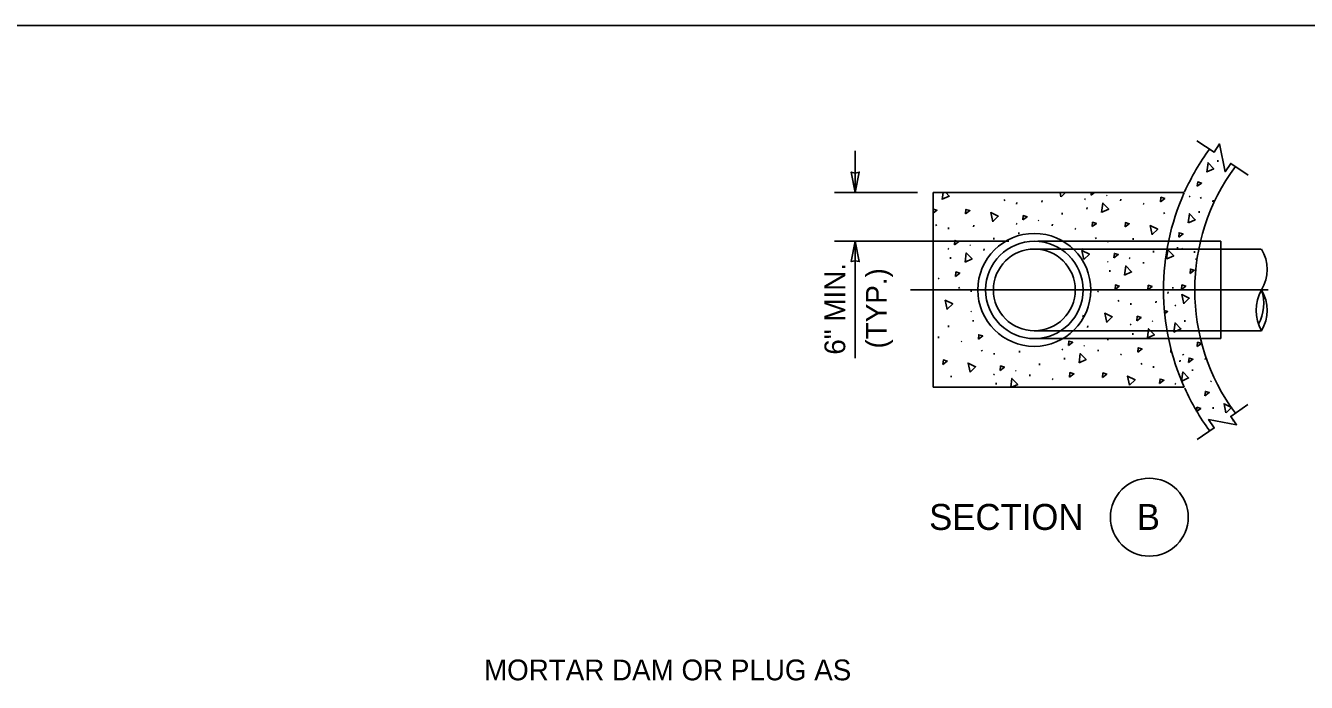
# Model space of a CAD drawing. Extents: x 99862 to 103151, y 100000 to 102076.
# Drawn here: x 101274 to 102261, y 101570 to 102076 of the extents above; entities that cross this region are included whole.
import ezdxf

# ---------------------------------------------------------------- set-up
doc = ezdxf.new("R2010")
doc.units = 0
for name, color, linetype in [('Level 1', 7, 'Continuous'), ('Level 15', 7, 'Continuous'), ('Level 17', 7, 'Continuous'), ('Level 19', 7, 'Continuous'), ('Level 20', 7, 'Continuous'), ('Level 27', 7, 'Continuous'), ('Level 9', 7, 'Continuous')]:
    doc.layers.add(name, color=color, linetype=linetype)

msp = doc.modelspace()

# ---------------------------------------------------------------- linework, layer by layer
at = {"layer": 'Level 1'}
for p, q in [((102051.16, 101903.5), (102194.29, 101903.5)), ((102179.16, 101909.5), (102053.84, 101909.5)), ((102194.7, 101909.5), (102179.16, 101909.5)), ((102194.7, 101909.5), (102194.7, 101834.5)), ((102194.75, 101903.5), (102225.99, 101903.5)), ((102231.31, 101872), (101955.67, 101872)), ((102051.16, 101840.5), (102194.29, 101840.5)), ((102179.16, 101834.5), (102053.84, 101834.5)), ((102194.7, 101834.5), (102179.16, 101834.5)), ((102194.98, 101840.5), (102226.21, 101840.5))]:
    msp.add_line(p, q, dxfattribs=at)
msp.add_lwpolyline([(99862, 99999.5), (103151, 99999.5), (103151, 102075.5), (99862, 102075.5)], close=True, dxfattribs=at)
for radius in [43.5, 37.5, 31.5]:
    msp.add_circle((102051.16, 101872), radius, dxfattribs=at)
for centre, radius, start, end in [((102334.48, 101872), 183.78, 143.86427, 155.72828), ((102334.48, 101872), 159.78, 143.51852, 216.48148), ((102198.94, 101887.75), 31.5, 330, 30), ((102253.49, 101856.25), 31.5, 150, 210), ((102194.23, 101861.5), 33.66, 331.70113, 18.1584), ((102198.94, 101856.25), 31.5, 330, 30), ((102334.48, 101872), 183.78, 204.34216, 216.23579)]:
    msp.add_arc(centre, radius, start, end, dxfattribs=at)
at = {"layer": 'Level 15'}
for p, q in [((101913.16, 101947), (101913.16, 101979)), ((101961.16, 101947), (101897.16, 101947)), ((102031.47, 101909.5), (101897.16, 101909.5)), ((101913.16, 101909.5), (101913.16, 101819.33))]:
    msp.add_line(p, q, dxfattribs=at)
for points in [[(102176.31, 101986.9), (102189.6, 101977.99), (102193.91, 101984.43), (102198.15, 101962.94), (102202.46, 101969.37), (102215.75, 101960.46)], [(102176.59, 101756.7), (102189.76, 101765.78), (102185.36, 101772.16), (102206.9, 101768.2), (102202.5, 101774.58), (102215.67, 101783.66)]]:
    msp.add_lwpolyline(points, dxfattribs=at)
for points in [[(101913.16, 101947), (101910.08, 101962.72), (101913.16, 101961.99), (101916.25, 101962.72)], [(101913.16, 101909.5), (101916.25, 101893.77), (101913.16, 101894.5), (101910.08, 101893.77)]]:
    msp.add_lwpolyline(points, close=True, dxfattribs=at)
at = {"layer": 'Level 17'}
for p, q in [((101973.16, 101947), (101973.16, 101797)), ((102166.7, 101947), (101973.16, 101947)), ((102166.7, 101797), (101973.16, 101797))]:
    msp.add_line(p, q, dxfattribs=at)
msp.add_arc((102334.48, 101872), 183.78, 155.91485, 204.08515, dxfattribs=at)
at = {"layer": 'Level 19'}
for p, q in [((102192.41, 101970.63), (102192.49, 101971.85)), ((102028.01, 101941.57), (102028.51, 101940.56)), ((102057.05, 101939.69), (102057.14, 101940.91)), ((102089.81, 101942.22), (102090.53, 101941.7)), ((102106.63, 101944.98), (102107.35, 101944.45)), ((102117.64, 101940.59), (102117.72, 101941.81)), ((102170.54, 101944.23), (102171.27, 101943.7)), ((102179.2, 101943.42), (102179.7, 101942.41)), ((102188.74, 101939.87), (102188.82, 101941.09)), ((102037.55, 101938.02), (102037.63, 101939.24)), ((102072.61, 101930.01), (102072.7, 101931.23)), ((102091.72, 101934.2), (102091.81, 101935.43)), ((102134.96, 101938.43), (102135.68, 101937.9)), ((102150.85, 101931.52), (102151.35, 101930.51)), ((102178.1, 101931.41), (102178.19, 101932.63)), ((101975.38, 101922.41), (101975.88, 101921.4)), ((101984.93, 101918.86), (101985.01, 101920.09)), ((102004.43, 101920.54), (102004.51, 101921.76)), ((102037.19, 101923.07), (102037.91, 101922.54)), ((102054, 101925.82), (102054.72, 101925.3)), ((102065.02, 101921.44), (102065.1, 101922.66)), ((102019.99, 101910.86), (102020.07, 101912.08)), ((102039.1, 101915.05), (102039.19, 101916.27)), ((102082.34, 101919.28), (102083.06, 101918.75)), ((102098.23, 101912.37), (102098.73, 101911.36)), ((102107.77, 101908.82), (102107.85, 101910.04)), ((102127.27, 101910.49), (102127.36, 101911.72)), ((101984.56, 101903.92), (101985.28, 101903.39)), ((102001.38, 101906.67), (102002.1, 101906.14)), ((102012.39, 101902.29), (102012.48, 101903.51)), ((102142.83, 101900.81), (102142.92, 101902.04)), ((102161.49, 101903.72), (102161.57, 101904.94)), ((102164.89, 101904.2), (102165.39, 101903.19)), ((102174.43, 101900.65), (102174.52, 101901.87)), ((101986.48, 101895.9), (101986.57, 101897.12)), ((102107.41, 101893.88), (102108.13, 101893.35)), ((102124.22, 101896.63), (102124.94, 101896.1)), ((102135.24, 101892.24), (102135.32, 101893.47)), ((102175.39, 101896.01), (102176.11, 101895.48)), ((101977.09, 101880.97), (101977.81, 101880.44)), ((102109.32, 101885.85), (102109.41, 101887.08)), ((101992.98, 101874.07), (101993.48, 101873.05)), ((102002.52, 101870.51), (102002.61, 101871.74)), ((102082.61, 101873.09), (102082.7, 101874.31)), ((102099.94, 101870.93), (102100.66, 101870.4)), ((102157.82, 101872.96), (102157.91, 101874.18)), ((102115.83, 101864.02), (102116.32, 101863.01)), ((102125.37, 101860.47), (102125.45, 101861.69)), ((102144.87, 101862.15), (102144.95, 101863.37)), ((102154.08, 101869.29), (102154.16, 101870.52)), ((102002.16, 101855.57), (102002.88, 101855.04)), ((102159.47, 101860.25), (102160.19, 101859.72)), ((101984.96, 101843.35), (101985.05, 101844.58)), ((102004.08, 101847.55), (102004.16, 101848.77)), ((102092.24, 101842.99), (102092.33, 101844.22)), ((102125, 101845.53), (102125.73, 101845)), ((102141.82, 101848.28), (102142.54, 101847.75)), ((102167.03, 101847.42), (102167.11, 101848.64)), ((101977.37, 101834.78), (101977.45, 101836.01)), ((101994.69, 101832.62), (101995.41, 101832.09)), ((102107.81, 101833.31), (102107.89, 101834.53)), ((102126.92, 101837.51), (102127.01, 101838.73)), ((102010.58, 101825.72), (102011.08, 101824.71)), ((102020.12, 101822.17), (102020.2, 101823.39)), ((102039.62, 101823.84), (102039.71, 101825.06)), ((102072.38, 101826.37), (102073.1, 101825.84)), ((102089.2, 101829.13), (102089.92, 101828.6)), ((102100.21, 101824.74), (102100.29, 101825.96)), ((102117.53, 101822.58), (102118.26, 101822.05)), ((102165.47, 101822.41), (102166.19, 101821.88)), ((102055.18, 101814.16), (102055.27, 101815.38)), ((102074.3, 101818.35), (102074.38, 101819.58)), ((102133.42, 101815.67), (102133.92, 101814.66)), ((102142.96, 101812.12), (102143.05, 101813.34)), ((102163.36, 101816.66), (102163.44, 101817.88)), ((102182.86, 101818.34), (102182.95, 101819.56)), ((101987, 101804.69), (101987.08, 101805.91)), ((102019.76, 101807.22), (102020.48, 101806.69)), ((102036.58, 101809.97), (102037.3, 101809.44)), ((102047.59, 101805.59), (102047.67, 101806.81)), ((102064.91, 101803.43), (102065.63, 101802.9)), ((102173.03, 101809.58), (102173.11, 101810.8)), ((102186.93, 101801.87), (102187.65, 101801.34)), ((102021.67, 101799.2), (102021.76, 101800.42)), ((102142.6, 101797.18), (102142.85, 101797)), ((102159.42, 101799.93), (102160.14, 101799.4)), ((102188.86, 101780.5), (102188.94, 101781.72)), ((102204.42, 101770.81), (102204.51, 101772.04))]:
    msp.add_line(p, q, dxfattribs=at)
for points in [[(102183.98, 101962.75), (102184.97, 101969.86), (102189.42, 101965.26), (102184.1, 101962.8)], [(102176.68, 101951.76), (102177.02, 101955.19), (102179.99, 101954.29), (102176.68, 101951.76)], [(101980.17, 101941.74), (101980.9, 101947)], [(101982.95, 101947), (101985.61, 101944.25), (101980.29, 101941.79)], [(102071.7, 101943.66), (102070.98, 101947)], [(102075.08, 101947), (102071.8, 101943.74)], [(102094.87, 101944.99), (102095.07, 101947)], [(102097.5, 101947), (102094.87, 101944.99)], [(102148.34, 101939.86), (102148.67, 101943.29), (102151.65, 101942.39), (102148.34, 101939.86)], [(101973.16, 101933.7), (101973.21, 101934.18), (101976.18, 101933.28), (101973.16, 101930.97)], [(101998.18, 101930.5), (101998.52, 101933.93), (102001.49, 101933.03), (101998.18, 101930.5)], [(102019.08, 101924.5), (102017.58, 101931.52), (102023.33, 101928.72), (102019.18, 101924.58)], [(102103.01, 101931.7), (102104, 101938.8), (102108.45, 101934.21), (102103.13, 101931.74)], [(102169.68, 101923.53), (102170.66, 101930.63), (102175.12, 101926.04), (102169.79, 101923.57)], [(102042.25, 101925.84), (102042.59, 101929.27), (102045.56, 101928.37), (102042.25, 101925.84)], [(102095.71, 101920.71), (102096.05, 101924.14), (102099.02, 101923.23), (102095.71, 101920.71)], [(102121.02, 101920.46), (102121.36, 101923.89), (102124.33, 101922.99), (102121.02, 101920.46)], [(102141.92, 101914.46), (102140.42, 101921.47), (102146.18, 101918.67), (102142.02, 101914.54)], [(101989.62, 101906.68), (101989.96, 101910.11), (101992.94, 101909.21), (101989.62, 101906.68)], [(102162.38, 101912.53), (102162.71, 101915.96), (102165.69, 101915.06), (102162.38, 101912.53)], [(101997.77, 101893.4), (101998.75, 101900.5), (102003.21, 101895.9), (101997.88, 101893.44)], [(102089.3, 101895.31), (102087.8, 101902.32), (102093.55, 101899.52), (102089.4, 101895.39)], [(102153.07, 101895.84), (102154.05, 101902.94), (102158.5, 101898.35), (102153.18, 101895.88)], [(102112.47, 101896.64), (102112.81, 101900.07), (102115.78, 101899.17), (102112.47, 101896.64)], [(102120.61, 101883.35), (102121.6, 101890.45), (102126.05, 101885.86), (102120.73, 101883.4)], [(101990.47, 101882.4), (101990.8, 101885.83), (101993.78, 101884.93), (101990.47, 101882.4)], [(102171.08, 101884.6), (102171.42, 101888.03), (102174.39, 101887.13), (102171.08, 101884.6)], [(102113.31, 101872.36), (102113.65, 101875.79), (102116.62, 101874.89), (102113.31, 101872.36)], [(102138.62, 101872.11), (102138.96, 101875.54), (102141.93, 101874.64), (102138.62, 101872.11)], [(102164.49, 101872.42), (102164.83, 101875.85), (102167.8, 101874.95), (102164.49, 101872.42)], [(101984.05, 101857), (101982.55, 101864.02), (101988.31, 101861.22), (101984.15, 101857.08)], [(102166.2, 101861.39), (102164.7, 101868.4), (102170.46, 101865.6), (102166.3, 101861.47)], [(102106.89, 101846.96), (102105.39, 101853.97), (102111.15, 101851.17), (102106.99, 101847.04)], [(102130.06, 101848.29), (102130.4, 101851.72), (102133.38, 101850.82), (102130.06, 101848.29)], [(102151.25, 101856.12), (102153.77, 101855.36), (102151.61, 101853.71)], [(102138.21, 101835), (102139.19, 101842.11), (102143.65, 101837.51), (102138.32, 101835.05)], [(102158.6, 101839.54), (102159.59, 101846.64), (102164.04, 101842.05), (102158.72, 101839.58)], [(102008.07, 101834.05), (102008.4, 101837.48), (102011.38, 101836.58), (102008.07, 101834.05)], [(102077.44, 101829.14), (102077.78, 101832.57), (102080.76, 101831.67), (102077.44, 101829.14)], [(102176.61, 101828.3), (102176.95, 101831.73), (102179.92, 101830.83), (102176.61, 101828.3)], [(102085.59, 101815.85), (102086.57, 101822.95), (102091.02, 101818.36), (102085.7, 101815.89)], [(102130.91, 101824.01), (102131.24, 101827.44), (102134.22, 101826.54), (102130.91, 101824.01)], [(102156.22, 101823.76), (102156.43, 101825.89)], [(102156.95, 101824.32), (102156.22, 101823.76)], [(101980.75, 101814.65), (101981.09, 101818.08), (101984.06, 101817.18), (101980.75, 101814.65)], [(102001.65, 101808.65), (102000.15, 101815.67), (102005.9, 101812.87), (102001.75, 101808.73)], [(102024.82, 101809.99), (102025.16, 101813.42), (102028.13, 101812.52), (102024.82, 101809.99)], [(102170.03, 101816.12), (102170.37, 101819.55), (102173.34, 101818.65), (102170.03, 101816.12)], [(102033, 101797), (102033.95, 101803.8), (102038.4, 101799.2), (102033.63, 101797)], [(102078.29, 101804.85), (102078.62, 101808.28), (102081.6, 101807.38), (102078.29, 101804.85)], [(102103.6, 101804.61), (102103.94, 101808.04), (102106.91, 101807.14), (102103.6, 101804.61)], [(102124.49, 101798.61), (102122.99, 101805.62), (102128.75, 101802.82), (102124.59, 101798.69)], [(102147.66, 101799.94), (102148, 101803.37), (102150.98, 101802.47), (102147.66, 101799.94)], [(102164.6, 101801.7), (102165.59, 101808.8), (102170.04, 101804.21), (102164.72, 101801.74)], [(102182.61, 101790.46), (102182.95, 101793.89), (102185.92, 101792.99), (102182.61, 101790.46)], [(102198.78, 101777.3), (102197.28, 101784.31), (102203.04, 101781.51), (102198.88, 101777.38)], [(102176.03, 101778.28), (102176.37, 101781.71), (102179.34, 101780.81), (102176.03, 101778.28)]]:
    msp.add_lwpolyline(points, dxfattribs=at)
at = {"layer": 'Level 27'}
for p, q in [((102089.12, 101903.88), (102088.63, 101902.76)), ((102078.59, 101897.37), (102078.55, 101897.3)), ((102089.12, 101852.43), (102088.63, 101851.31))]:
    msp.add_line(p, q, dxfattribs=at)
at = {"layer": 'Level 9'}
msp.add_circle((102139.72, 101697), 30, dxfattribs=at)

# ---------------------------------------------------------------- texts
at = {"layer": 'Level 20'}
for s, p in [('6" MIN.', (101905.52, 101822.14)), ('(TYP.)', (101937.52, 101826.9))]:
    msp.add_text(s, height=16, rotation=90, dxfattribs=at).set_placement(p)
for s, height, p in [('SECTION', 20, (101970.13, 101687.18)), ('B', 20, (102130.08, 101687.18)), ('MORTAR DAM OR PLUG AS', 16, (101627.24, 101571.39))]:
    msp.add_text(s, height=height, dxfattribs=at).set_placement(p)

doc.saveas('drawing.dxf')
